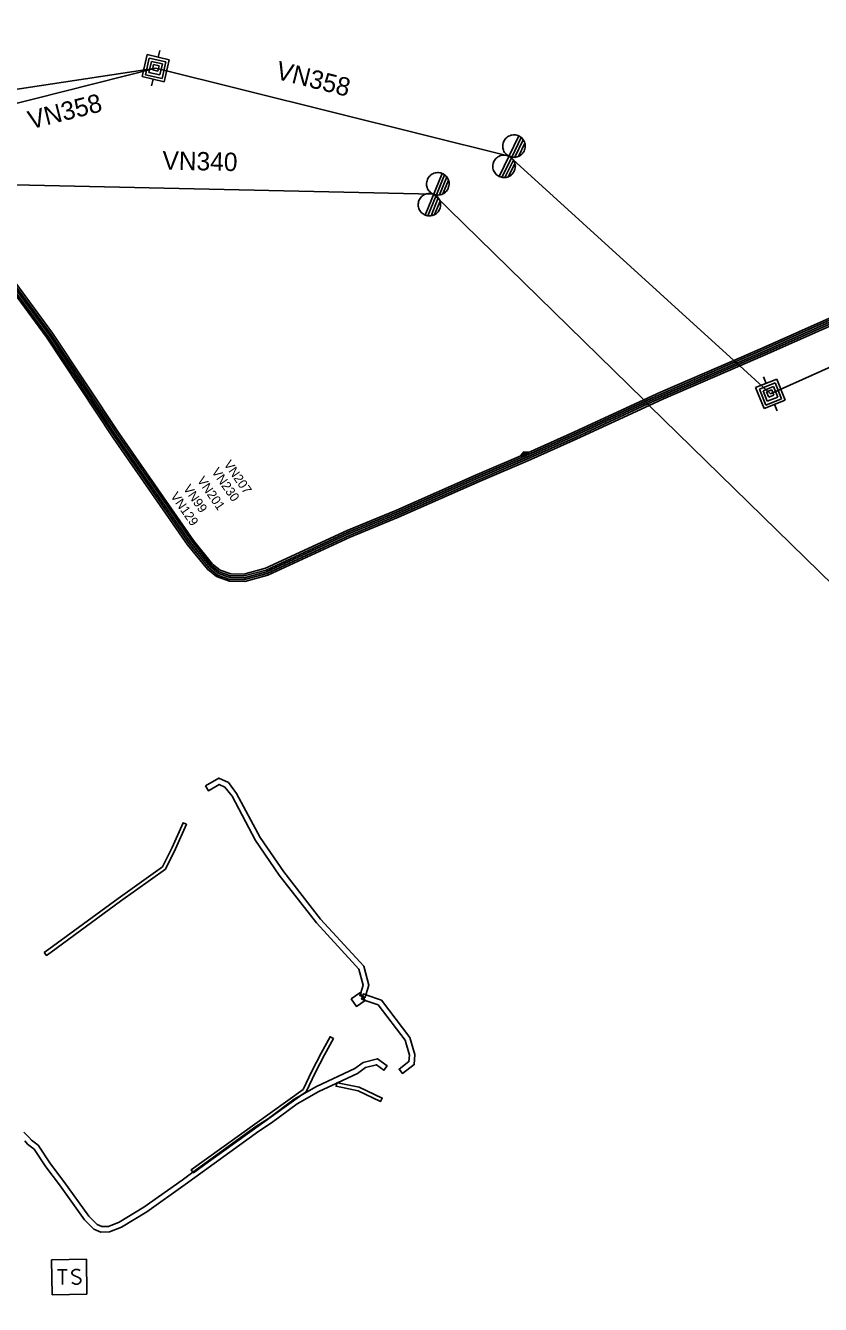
# Model space of a CAD drawing. Extents: x -643811 to -636362, y -1117362 to -1108614.
# Drawn here: x -640859.1 to -640773, y -1116043.8 to -1115905.2 of the extents above; entities that cross this region are included whole.
import ezdxf

# ---------------------------------------------------------------- set-up
doc = ezdxf.new("R2010")
doc.units = 0
for name, color, linetype in [('1', 7, 'Continuous'), ('13', 7, 'Continuous'), ('19', 7, 'Continuous'), ('20', 7, 'Continuous'), ('25', 7, 'Continuous'), ('3', 7, 'Continuous'), ('4', 7, 'Continuous'), ('5', 7, 'Continuous'), ('7', 7, 'Continuous')]:
    doc.layers.add(name, color=color, linetype=linetype)

# ---------------------------------------------------------------- blocks, each defined once
blk = doc.blocks.new('VN450')
at = {"layer": '13'}
for points in [[(0, 0), (-0.01, 0.13), (-0.03, 0.25), (-0.06, 0.38), (-0.11, 0.5), (-0.16, 0.61), (-0.23, 0.72), (-0.31, 0.82), (-0.4, 0.91), (-0.5, 0.99), (-0.61, 1.06), (-0.72, 1.11), (-0.84, 1.16), (-0.97, 1.19), (-1.09, 1.21), (-1.22, 1.22), (-1.35, 1.21), (-1.47, 1.19), (-1.59, 1.16), (-1.71, 1.11), (-1.83, 1.06), (-1.93, 0.99), (-2.03, 0.91), (-2.12, 0.82), (-2.2, 0.72), (-2.27, 0.61), (-2.33, 0.5), (-2.38, 0.38), (-2.41, 0.25), (-2.43, 0.13), (-2.44, 0), (-2.43, -0.13), (-2.41, -0.25), (-2.38, -0.38), (-2.33, -0.5), (-2.27, -0.61), (-2.2, -0.72), (-2.12, -0.82), (-2.03, -0.91), (-1.93, -0.99), (-1.83, -1.06), (-1.71, -1.11), (-1.59, -1.16), (-1.47, -1.19), (-1.35, -1.21), (-1.22, -1.22), (-1.09, -1.21), (-0.97, -1.19), (-0.84, -1.16), (-0.72, -1.11), (-0.61, -1.06), (-0.5, -0.99), (-0.4, -0.91), (-0.31, -0.82), (-0.23, -0.72), (-0.16, -0.61), (-0.11, -0.5), (-0.06, -0.38), (-0.03, -0.25), (-0.01, -0.13), (0, 0)], [(-2.44, 0), (2.44, 0)], [(2.44, 0), (2.43, 0.13), (2.41, 0.25), (2.38, 0.38), (2.33, 0.5), (2.27, 0.61), (2.2, 0.72), (2.12, 0.82), (2.03, 0.91), (1.94, 0.99), (1.83, 1.06), (1.71, 1.11), (1.6, 1.16), (1.47, 1.19), (1.35, 1.21), (1.22, 1.22), (1.09, 1.21), (0.97, 1.19), (0.84, 1.16), (0.72, 1.11), (0.61, 1.06), (0.5, 0.99), (0.4, 0.91), (0.31, 0.82), (0.23, 0.72), (0.16, 0.61), (0.11, 0.5), (0.06, 0.38), (0.03, 0.25), (0.01, 0.13), (0, 0), (0.01, -0.13), (0.03, -0.25), (0.06, -0.38), (0.11, -0.5), (0.16, -0.61), (0.23, -0.72), (0.31, -0.82), (0.4, -0.91), (0.5, -0.99), (0.61, -1.06), (0.72, -1.11), (0.84, -1.16), (0.97, -1.19), (1.09, -1.21), (1.22, -1.22), (1.35, -1.21), (1.47, -1.19), (1.6, -1.16), (1.71, -1.11), (1.83, -1.06), (1.94, -0.99), (2.03, -0.91), (2.12, -0.82), (2.2, -0.72), (2.27, -0.61), (2.33, -0.5), (2.38, -0.38), (2.41, -0.25), (2.43, -0.13), (2.44, 0)], [(-2.4, -0.31), (-0.04, -0.31)], [(-2.26, -0.61), (-0.17, -0.61)], [(-2.01, -0.92), (-0.42, -0.92)], [(0.04, -0.31), (2.4, -0.31)], [(0.17, -0.61), (2.27, -0.61)], [(0.42, -0.92), (2.02, -0.92)]]:
    blk.add_lwpolyline(points, dxfattribs=at)
blk = doc.blocks.new('VN470')
at = {"layer": '13'}
for points in [[(0, 1.22), (0, 1.97)], [(-1.23, 1.22), (1.23, 1.22)], [(-1.23, -1.23), (-1.23, 1.22)], [(-0.92, 0.9), (0.92, 0.9)], [(-0.92, -0.95), (-0.92, 0.9)], [(-0.61, 0.61), (0.61, 0.61)], [(-0.61, -0.62), (-0.61, 0.61)], [(-0.31, -0.27), (-0.31, 0.34)], [(-0.31, 0.34), (0.31, 0.34)], [(0.31, 0.34), (0.31, -0.27)], [(0.61, 0.61), (0.61, -0.62)], [(0.92, 0.9), (0.92, -0.95)], [(1.23, 1.22), (1.23, -1.23)], [(1.23, -1.23), (-1.23, -1.23)], [(0.92, -0.95), (-0.92, -0.95)], [(0.61, -0.62), (-0.61, -0.62)], [(0.31, -0.27), (-0.31, -0.27)], [(0, -1.23), (0, -1.98)]]:
    blk.add_lwpolyline(points, dxfattribs=at)
blk = doc.blocks.new('VN870')
at = {"layer": '19'}
for points in [[(0, -0.25), (0.5, 0), (0, 0.25), (-0.5, 0), (0, -0.25)], [(0.37, 0), (0, 0.19), (-0.36, 0), (0, -0.19), (0.37, 0)], [(0.24, 0), (0, 0.12), (-0.25, 0), (0, -0.12), (0.24, 0)], [(0.12, 0), (0, 0.06), (-0.13, 0), (0, -0.06), (0.12, 0)]]:
    blk.add_lwpolyline(points, dxfattribs=at)
blk = doc.blocks.new('VN640')
at = {"layer": '25'}
for points in [[(-1.89, 1.89), (1.89, 1.89)], [(-1.89, -1.89), (-1.89, 1.89)], [(1.89, 1.89), (1.89, -1.89)], [(-1.26, 0.79), (-0.22, 0.79)], [(-0.73, 0.79), (-0.73, -0.79)], [(1.2, 0.66), (0.94, 0.79), (0.66, 0.79), (0.41, 0.66), (0.28, 0.47), (0.28, 0.41), (0.41, 0.22), (1.13, -0.16), (1.26, -0.32), (1.26, -0.47), (1.13, -0.66), (0.91, -0.79), (0.63, -0.79), (0.5, -0.73), (0.28, -0.6)], [(1.89, -1.89), (-1.89, -1.89)]]:
    blk.add_lwpolyline(points, dxfattribs=at)

msp = doc.modelspace()

# ---------------------------------------------------------------- linework, layer by layer
at = {"layer": '1'}
for points in [[(-640174.13, -1115803.89), (-640251.81, -1115797.69), (-640320.19, -1115797.01), (-640382.28, -1115796.07), (-640441.87, -1115795.49), (-640509.03, -1115825.24), (-640529.18, -1115834.18), (-640529.51, -1115834.33), (-640569.54, -1115852.09), (-640642.67, -1115884.59), (-640695.7, -1115908.15), (-640695.88, -1115908.23), (-640712.05, -1115915.41), (-640778.4, -1115945.12), (-640781.72, -1115942.1), (-640781.89, -1115941.95), (-640782.05, -1115941.8), (-640782.21, -1115941.65), (-640782.37, -1115941.51), (-640806.72, -1115919.38), (-640845, -1115909.84)], [(-640845, -1115909.84), (-640871.74, -1115916.61), (-640871.94, -1115916.66), (-640872.15, -1115916.71), (-640872.35, -1115916.76), (-640872.56, -1115916.81), (-640875.9, -1115917.66), (-640894.09, -1115922.37), (-640894.09, -1115922.37), (-640894.09, -1115922.37)], [(-640702.68, -1116085.01), (-640737.68, -1116023.02), (-640768.51, -1115968.89), (-640791.52, -1115946.37), (-640791.67, -1115946.22), (-640791.83, -1115946.07), (-640791.98, -1115945.92), (-640792.13, -1115945.77), (-640814.89, -1115923.5), (-640865.16, -1115922.36), (-640867.29, -1115922.81), (-640867.51, -1115922.86), (-640867.72, -1115922.9), (-640867.94, -1115922.95), (-640868.15, -1115922.99), (-640887.58, -1115927.09), (-640888.87, -1115927.37), (-640890.12, -1115927.63)]]:
    msp.add_lwpolyline(points, dxfattribs=at)
at = {"layer": '20'}
for points in [[(-640839.59, -1115987.59), (-640838.15, -1115986.75), (-640837.12, -1115987.23), (-640836.23, -1115988.4), (-640833.67, -1115993.19), (-640831.13, -1115996.89), (-640827.13, -1116002.03), (-640823.27, -1116006.23), (-640822.46, -1116007.13), (-640821.9, -1116009.16), (-640822.22, -1116010.22), (-640822.3, -1116010.5), (-640822.59, -1116010.41), (-640822.88, -1116010.32), (-640822.81, -1116010.1), (-640822.52, -1116009.16), (-640823, -1116007.43), (-640823.71, -1116006.63), (-640827.59, -1116002.41), (-640831.61, -1115997.25), (-640834.19, -1115993.51), (-640836.73, -1115988.72), (-640837.5, -1115987.71), (-640838.11, -1115987.43), (-640839.29, -1115988.11)], [(-640857.08, -1116005.64), (-640856.57, -1116005.27), (-640849.05, -1115999.77), (-640844.25, -1115996.34), (-640843.23, -1115994.26), (-640842.04, -1115991.58), (-640841.68, -1115991.74), (-640842.87, -1115994.42), (-640843.93, -1115996.6), (-640848.81, -1116000.09), (-640856.33, -1116005.59), (-640856.84, -1116005.96)], [(-640823.83, -1116010.66), (-640822.88, -1116010), (-640822.81, -1116010.1), (-640822.59, -1116010.41), (-640822.3, -1116010.82), (-640822.31, -1116010.82), (-640823.25, -1116011.48)], [(-640822.59, -1116010.41), (-640822.49, -1116010.13), (-640822.22, -1116010.22), (-640820.54, -1116010.81), (-640817.45, -1116014.84), (-640816.92, -1116016.7), (-640816.98, -1116017.78), (-640818.27, -1116018.74), (-640818.63, -1116018.26), (-640817.56, -1116017.46), (-640817.52, -1116016.76), (-640817.99, -1116015.12), (-640820.9, -1116011.31), (-640822.31, -1116010.82), (-640822.69, -1116010.69)], [(-640840.97, -1116029.43), (-640841.16, -1116029.18), (-640839.51, -1116027.99), (-640829.02, -1116020.46), (-640828.1, -1116018.49), (-640827.06, -1116016.54), (-640826.11, -1116014.77), (-640825.75, -1116014.96), (-640826.7, -1116016.72), (-640827.74, -1116018.67), (-640828.7, -1116020.72), (-640829.18, -1116021.06), (-640839.27, -1116028.31), (-640840.92, -1116029.5)], [(-640825.38, -1116019.79), (-640825.37, -1116019.73), (-640825.3, -1116019.75), (-640822.96, -1116020.24), (-640820.46, -1116021.41), (-640820.63, -1116021.77), (-640823.08, -1116020.62), (-640825.45, -1116020.13)]]:
    msp.add_lwpolyline(points, close=True, dxfattribs=at)
msp.add_lwpolyline([(-640859.29, -1116025.09), (-640858.73, -1116025.63), (-640858.46, -1116025.95), (-640857.73, -1116026.51), (-640856.4, -1116028.52), (-640854.96, -1116030.43), (-640852.24, -1116034.2), (-640851.35, -1116035.1), (-640850.82, -1116035.32), (-640850.13, -1116035.31), (-640848.96, -1116034.85), (-640846.3, -1116033.21), (-640842.14, -1116030.29), (-640840.97, -1116029.43), (-640834.16, -1116024.48), (-640832.78, -1116023.6), (-640830.01, -1116021.54), (-640829.18, -1116021.06), (-640827.59, -1116020.16), (-640823.43, -1116018.21), (-640822.52, -1116017.55), (-640820.97, -1116017.14), (-640819.92, -1116017.92), (-640820.28, -1116018.4), (-640821.09, -1116017.8), (-640822.26, -1116018.11), (-640823.13, -1116018.73), (-640825.3, -1116019.75), (-640825.38, -1116019.79), (-640827.31, -1116020.7), (-640829.69, -1116022.04), (-640832.44, -1116024.1), (-640833.82, -1116024.98), (-640841.8, -1116030.77), (-640845.96, -1116033.71), (-640848.7, -1116035.39), (-640850.01, -1116035.91), (-640850.94, -1116035.92), (-640851.69, -1116035.6), (-640852.7, -1116034.58), (-640855.44, -1116030.79), (-640856.9, -1116028.86), (-640858.17, -1116026.93), (-640858.88, -1116026.39), (-640859.17, -1116026.05)], dxfattribs=at)
at = {"layer": '4'}
msp.add_lwpolyline([(-640845, -1115909.84), (-640873.36, -1115914.15), (-640873.58, -1115914.19), (-640873.8, -1115914.22), (-640874.02, -1115914.25), (-640874.24, -1115914.29), (-640877.61, -1115914.8)], dxfattribs=at)
at = {"layer": '5'}
for points in [[(-640860.49, -1115933.35), (-640856.52, -1115938.77), (-640849.28, -1115949.66), (-640841.22, -1115961.24), (-640839.11, -1115963.84), (-640838.21, -1115964.57), (-640836.92, -1115965.02), (-640835.41, -1115965.05), (-640832.98, -1115964.4), (-640824.1, -1115960.28), (-640818.84, -1115958.12), (-640810.01, -1115954.22), (-640804.53, -1115951.87), (-640799.54, -1115949.62), (-640791.83, -1115946.07), (-640790.13, -1115945.29), (-640782.05, -1115941.8), (-640778.8, -1115940.4), (-640764.54, -1115934.05)], [(-640860.33, -1115933.23), (-640856.36, -1115938.65), (-640849.12, -1115949.55), (-640841.06, -1115961.12), (-640838.97, -1115963.7), (-640838.11, -1115964.39), (-640836.88, -1115964.82), (-640835.43, -1115964.85), (-640833.05, -1115964.21), (-640824.18, -1115960.1), (-640818.92, -1115957.94), (-640810.09, -1115954.04), (-640804.61, -1115951.69), (-640799.62, -1115949.44), (-640791.98, -1115945.92), (-640790.21, -1115945.11), (-640782.21, -1115941.65), (-640778.88, -1115940.22), (-640764.62, -1115933.87)], [(-640860.16, -1115933.12), (-640856.19, -1115938.54), (-640848.95, -1115949.43), (-640840.9, -1115961), (-640838.83, -1115963.56), (-640838.01, -1115964.22), (-640836.85, -1115964.62), (-640835.46, -1115964.65), (-640833.12, -1115964.02), (-640824.26, -1115959.91), (-640819, -1115957.75), (-640810.17, -1115953.85), (-640804.69, -1115951.5), (-640799.71, -1115949.26), (-640792.13, -1115945.77), (-640790.29, -1115944.93), (-640782.37, -1115941.51), (-640778.96, -1115940.03), (-640764.7, -1115933.69)], [(-640860.82, -1115933.58), (-640856.85, -1115939), (-640849.61, -1115949.89), (-640841.54, -1115961.48), (-640839.39, -1115964.12), (-640838.41, -1115964.92), (-640836.99, -1115965.42), (-640835.36, -1115965.45), (-640832.84, -1115964.78), (-640823.94, -1115960.65), (-640818.68, -1115958.49), (-640809.85, -1115954.59), (-640804.37, -1115952.24), (-640799.37, -1115949.98), (-640791.52, -1115946.37), (-640789.97, -1115945.66), (-640781.72, -1115942.1), (-640778.64, -1115940.77), (-640764.37, -1115934.42)], [(-640860.65, -1115933.46), (-640856.68, -1115938.88), (-640849.44, -1115949.77), (-640841.38, -1115961.36), (-640839.25, -1115963.98), (-640838.31, -1115964.75), (-640836.96, -1115965.22), (-640835.39, -1115965.25), (-640832.91, -1115964.59), (-640824.02, -1115960.46), (-640818.76, -1115958.3), (-640809.93, -1115954.4), (-640804.45, -1115952.05), (-640799.46, -1115949.8), (-640791.67, -1115946.22), (-640790.05, -1115945.47), (-640781.89, -1115941.95), (-640778.72, -1115940.58), (-640764.46, -1115934.23)]]:
    msp.add_lwpolyline(points, dxfattribs=at)

# ---------------------------------------------------------------- block references
at = {"layer": '13'}
for name, p, rotation in [('VN470', (-640845, -1115909.84), -13.000000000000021), ('VN450', (-640806.72, -1115919.38), 64), ('VN450', (-640814.89, -1115923.5), 68), ('VN470', (-640778.4, -1115945.12), 21.999999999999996)]:
    msp.add_blockref(name, p, dxfattribs=dict(at, rotation=rotation))
at = {"layer": '19', "rotation": 24}
msp.add_blockref('VN870', (-640805.02, -1115951.64), dxfattribs=at)
at = {"layer": '25', "rotation": 1}
msp.add_blockref('VN640', (-640854.37, -1116040.78), dxfattribs=at)

# ---------------------------------------------------------------- texts
at = {"layer": '3'}
for s, rotation, p in [('VN358', 346.0072, (-640832.1, -1115910.98)), ('VN358', 14.2019, (-640858.55, -1115916.48)), ('VN340', 358.7066, (-640844.29, -1115920.82))]:
    msp.add_text(s, height=1.989, rotation=rotation, dxfattribs=at).set_placement(p)
at = {"layer": '7'}
for s, rotation, p in [('VN207', 304.8394, (-640837.67, -1115952.75)), ('VN201', 304.839, (-640840.56, -1115954.5)), ('VN230', 304.8386, (-640838.99, -1115953.56)), ('VN99', 304.8394, (-640842.06, -1115955.38)), ('VN129', 304.8385, (-640843.44, -1115956.2))]:
    msp.add_text(s, height=0.994, rotation=rotation, dxfattribs=at).set_placement(p)

doc.saveas('drawing.dxf')
